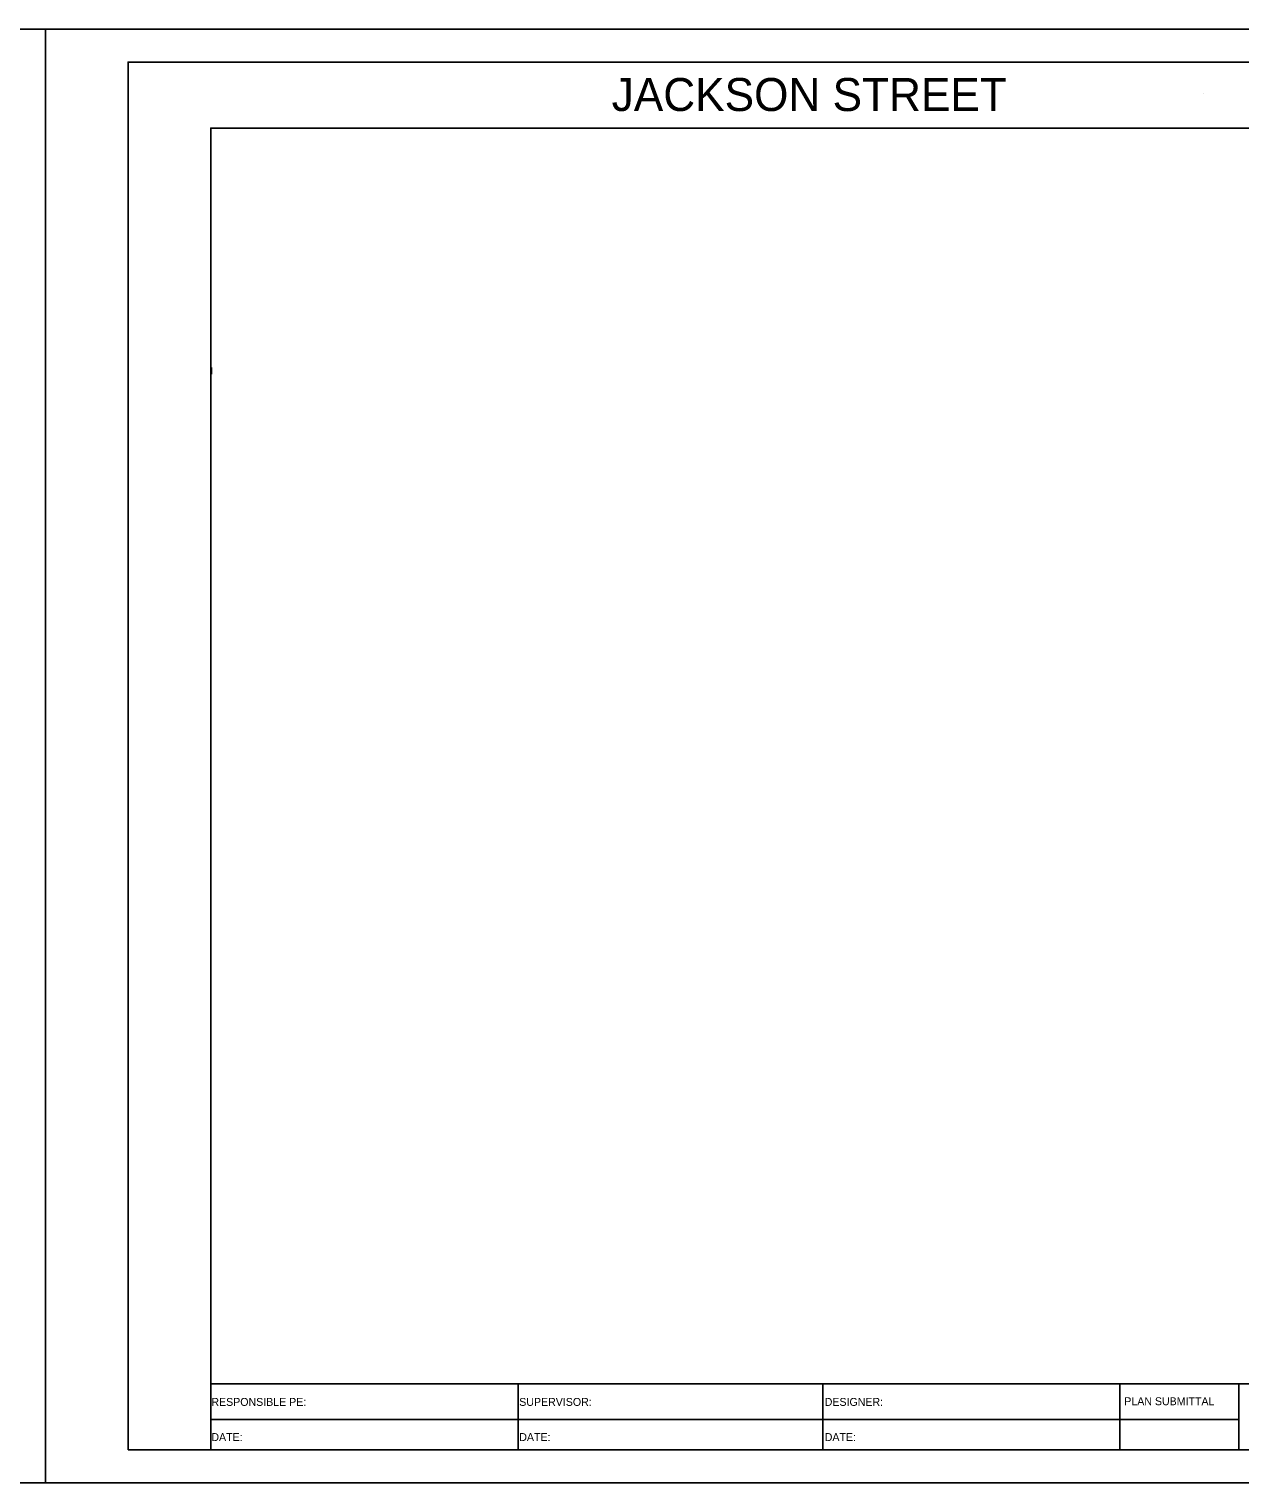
# Model space of a CAD drawing. Extents: x 1797478 to 1802796, y 246529 to 250952.
# Drawn here: x 1802453.5 to 1802636.8, y 250064.4 to 250284.4 of the extents above; entities that cross this region are included whole.
import ezdxf

# ---------------------------------------------------------------- set-up
doc = ezdxf.new("R2010")
doc.units = 0
for name, color, linetype in [('2', 7, 'Continuous'), ('ANNO-SHT', 7, 'Continuous'), ('ANNO-TXT', 7, 'Continuous'), ('AXIS', 7, 'Continuous'), ('DRAINAGE', 7, 'Continuous'), ('Level 1', 7, 'Continuous'), ('Level 62', 7, 'Continuous'), ('SHT-BDR', 7, 'Continuous'), ('SHT-BNDRY', 7, 'Continuous')]:
    doc.layers.add(name, color=color, linetype=linetype)

# ---------------------------------------------------------------- blocks, each defined once
blk = doc.blocks.new('SC47208')
at = {"layer": 'Level 1'}
blk.add_line((0, 0), (0, 0), dxfattribs=at)

msp = doc.modelspace()

# ---------------------------------------------------------------- linework, layer by layer
at = {"layer": '2'}
msp.add_lwpolyline([(1802481.12, 250233.21), (1802481.1, 250232.21)], dxfattribs=at)
msp.add_lwpolyline([(1802481.12, 250233.21), (1802481.1, 250232.21)], dxfattribs=at)
at = {"layer": 'AXIS'}
msp.add_line((1802481, 250189.42), (1802481, 250189.43), dxfattribs=at)
at = {"layer": 'Level 62'}
for points in [[(1802116, 250064.42), (1802456, 250064.42), (1802456, 250284.42), (1802116, 250284.42)], [(1802456, 250064.42), (1802796, 250064.42), (1802796, 250284.42), (1802456, 250284.42)]]:
    msp.add_lwpolyline(points, close=True, dxfattribs=at)
at = {"layer": 'SHT-BDR'}
msp.add_lwpolyline([(1802481, 250079.43), (1802781, 250079.43), (1802781, 250269.43), (1802481, 250269.43)], close=True, dxfattribs=at)
at = {"layer": 'SHT-BNDRY'}
for p, q in [((1802481, 250069.42), (1802481, 250079.43)), ((1802527.52, 250079.43), (1802527.52, 250069.42)), ((1802573.67, 250069.42), (1802573.67, 250079.43)), ((1802618.59, 250069.42), (1802618.59, 250079.43)), ((1802636.63, 250069.42), (1802636.63, 250079.43)), ((1802481, 250074.03), (1802636.63, 250074.03))]:
    msp.add_line(p, q, dxfattribs=at)
msp.add_lwpolyline([(1802468.5, 250069.42), (1802791, 250069.42), (1802791, 250279.42), (1802468.5, 250279.42)], close=True, dxfattribs=at)

# ---------------------------------------------------------------- block references
at = {"layer": 'DRAINAGE', "xscale": 0.2, "yscale": 0.20000000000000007, "rotation": -116.41666666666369}
msp.add_blockref('SC47208', (1802631.32, 250274.62), dxfattribs=at)
msp.add_blockref('SC47208', (1802631.32, 250274.62), dxfattribs=at)

# ---------------------------------------------------------------- texts
at = {"layer": 'ANNO-SHT'}
msp.add_text('             JACKSON STREET             ', height=4.9995, rotation=360, dxfattribs=at).set_placement((1802517.55, 250272.02))
at = {"layer": 'ANNO-TXT'}
for s, p in [('RESPONSIBLE PE:', (1802481.1, 250076.08)), ('SUPERVISOR:', (1802527.7, 250076.08)), ('DESIGNER:', (1802573.94, 250076.08)), ('PLAN SUBMITTAL', (1802619.28, 250076.18)), ('DATE:', (1802481.1, 250070.76)), ('DATE:', (1802527.7, 250070.76)), ('DATE:', (1802573.94, 250070.76))]:
    msp.add_text(s, height=1.2, rotation=360, dxfattribs=at).set_placement(p)

doc.saveas('drawing.dxf')
